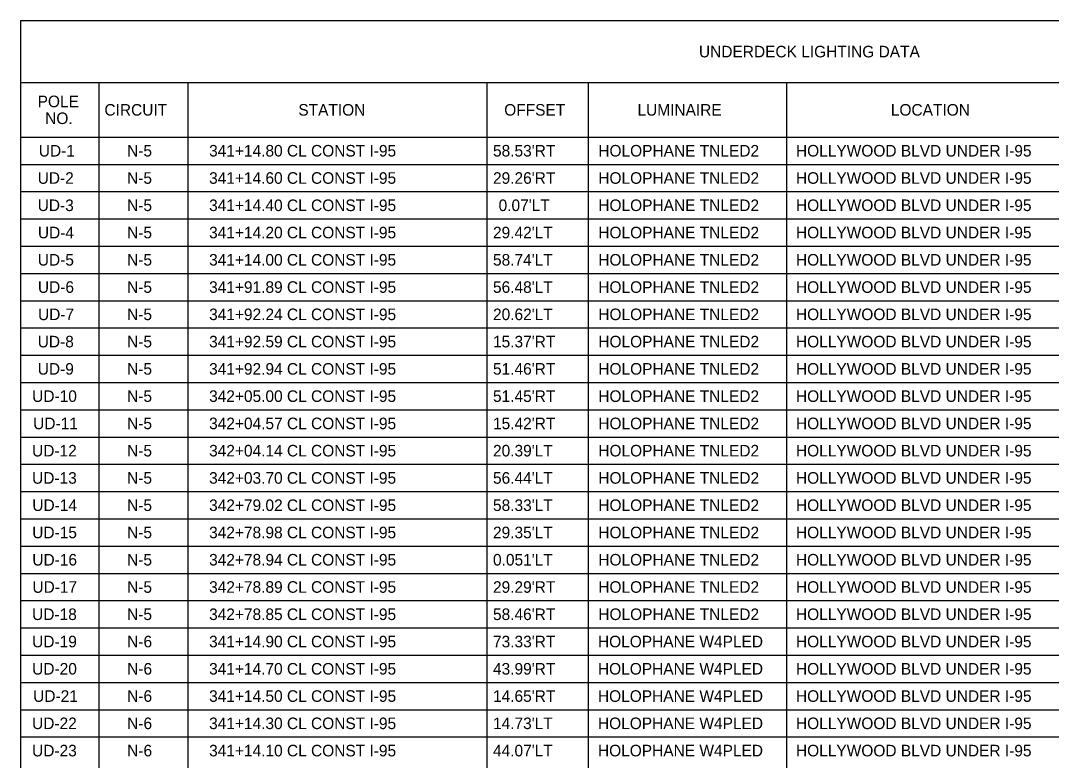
# Model space of a CAD drawing. Extents: x -816.7 to -727.6, y -2197.9 to -2187.8.
# Drawn here: x -777.1 to -770.86, y -2192.25 to -2187.77 of the extents above; entities that cross this region are included whole.
import ezdxf

# ---------------------------------------------------------------- set-up
doc = ezdxf.new("R2010")
doc.units = 0
for name, color, linetype in [('ClipBorder_dp', 7, 'Continuous'), ('MatchLines_dp', 7, 'Continuous'), ('NorthArw_dp', 7, 'Continuous'), ('Scale_dp', 7, 'Continuous')]:
    doc.layers.add(name, color=color, linetype=linetype)

msp = doc.modelspace()

# ---------------------------------------------------------------- linework, layer by layer
at = {"layer": 'MatchLines_dp'}
for p, q in [((-777.0968, -2188.4786), (-767.3318, -2188.4786)), ((-777.0968, -2188.6436), (-767.3318, -2188.6436)), ((-777.0968, -2188.6436), (-767.3318, -2188.6436)), ((-777.0968, -2188.8086), (-767.3318, -2188.8086)), ((-777.0968, -2188.8086), (-767.3318, -2188.8086)), ((-777.0968, -2188.9736), (-767.3318, -2188.9736)), ((-777.0968, -2188.9736), (-767.3318, -2188.9736)), ((-777.0968, -2189.1386), (-767.3318, -2189.1386)), ((-777.0968, -2189.1386), (-767.3318, -2189.1386)), ((-777.0968, -2189.3036), (-767.3318, -2189.3036)), ((-777.0968, -2189.3036), (-767.3318, -2189.3036)), ((-777.0968, -2189.4686), (-776.0843, -2189.4686)), ((-777.0968, -2189.4686), (-767.3318, -2189.4686)), ((-774.2768, -2189.4686), (-767.3318, -2189.4686)), ((-777.0968, -2189.6336), (-767.3318, -2189.6336)), ((-777.0968, -2189.6336), (-767.3318, -2189.6336)), ((-777.0968, -2189.7986), (-767.3318, -2189.7986)), ((-777.0968, -2189.7986), (-767.3318, -2189.7986)), ((-777.0968, -2189.9636), (-767.3318, -2189.9636)), ((-777.0968, -2189.9636), (-767.3318, -2189.9636)), ((-777.0968, -2190.1286), (-767.3318, -2190.1286)), ((-777.0968, -2190.1286), (-767.3318, -2190.1286)), ((-777.0968, -2190.2936), (-767.3318, -2190.2936)), ((-777.0968, -2190.2936), (-767.3318, -2190.2936)), ((-777.0968, -2190.4586), (-767.3318, -2190.4586)), ((-777.0968, -2190.4586), (-767.3318, -2190.4586)), ((-777.0968, -2190.6236), (-767.3318, -2190.6236)), ((-777.0968, -2190.6236), (-767.3318, -2190.6236)), ((-777.0968, -2190.7886), (-767.3318, -2190.7886)), ((-777.0968, -2190.7886), (-767.3318, -2190.7886)), ((-777.0968, -2190.9536), (-767.3318, -2190.9536)), ((-777.0968, -2190.9536), (-767.3318, -2190.9536)), ((-777.0968, -2191.1186), (-767.3318, -2191.1186)), ((-777.0968, -2191.1186), (-767.3318, -2191.1186)), ((-777.0968, -2191.2836), (-767.3318, -2191.2836)), ((-777.0968, -2191.2836), (-767.3318, -2191.2836)), ((-777.0968, -2191.4486), (-767.3318, -2191.4486)), ((-777.0968, -2191.4486), (-767.3318, -2191.4486)), ((-777.0968, -2191.6136), (-767.3318, -2191.6136)), ((-777.0968, -2191.6136), (-767.3318, -2191.6136)), ((-777.0968, -2191.7786), (-767.3318, -2191.7786)), ((-777.0968, -2191.7786), (-767.3318, -2191.7786)), ((-777.0968, -2191.9436), (-767.3318, -2191.9436)), ((-777.0968, -2191.9436), (-767.3318, -2191.9436)), ((-777.0968, -2192.1086), (-767.3318, -2192.1086)), ((-777.0968, -2192.1086), (-767.3318, -2192.1086))]:
    msp.add_line(p, q, dxfattribs=at)
at = {"layer": 'NorthArw_dp'}
for p, q in [((-777.0968, -2187.7736), (-767.3318, -2187.7736)), ((-777.0968, -2187.7736), (-777.0968, -2196.6761)), ((-777.0968, -2188.1486), (-767.3318, -2188.1486)), ((-777.0968, -2188.1486), (-767.3318, -2188.1486))]:
    msp.add_line(p, q, dxfattribs=at)
at = {"layer": 'Scale_dp'}
for p, q in [((-776.6243, -2188.1486), (-776.6243, -2196.6761)), ((-776.6243, -2188.1486), (-776.6243, -2196.6761)), ((-776.0843, -2188.1486), (-776.0843, -2196.6761)), ((-776.0843, -2188.1486), (-776.0843, -2196.6761)), ((-774.2768, -2188.1486), (-774.2768, -2189.3036)), ((-774.2768, -2188.1486), (-774.2768, -2196.6761)), ((-773.6618, -2188.1486), (-773.6618, -2196.6761)), ((-773.6618, -2188.1486), (-773.6618, -2196.6761)), ((-772.4618, -2188.1486), (-772.4618, -2196.6761)), ((-772.4618, -2188.1486), (-772.4618, -2196.6761)), ((-777.0968, -2188.4786), (-767.3318, -2188.4786)), ((-774.2768, -2189.4686), (-774.2768, -2196.6761))]:
    msp.add_line(p, q, dxfattribs=at)

# ---------------------------------------------------------------- texts
at = {"layer": 'ClipBorder_dp'}
for s, p in [('UNDERDECK LIGHTING DATA', (-772.9925, -2187.9961)), ('POLE', (-776.9939, -2188.2976)), ('CIRCUIT', (-776.5897, -2188.3486)), ('STATION', (-775.4164, -2188.3486)), ('OFFSET', (-774.1708, -2188.3486)), ('LUMINAIRE', (-773.3645, -2188.3486)), ('LOCATION', (-771.8315, -2188.3486)), ('NO.', (-776.9482, -2188.3996)), ('UD-1', (-776.9869, -2188.5961)), ('N-5', (-776.4526, -2188.5961)), ('341+14.80 CL CONST I-95', (-775.9564, -2188.5961)), ("58.53'RT", (-774.2386, -2188.5961)), ('HOLOPHANE TNLED2', (-773.6014, -2188.5961)), ('HOLLYWOOD BLVD UNDER I-95', (-772.4054, -2188.5961)), ('UD-2', (-776.9936, -2188.7611)), ('N-5', (-776.4526, -2188.7611)), ('341+14.60 CL CONST I-95', (-775.9564, -2188.7611)), ("29.26'RT", (-774.2386, -2188.7611)), ('HOLOPHANE TNLED2', (-773.6014, -2188.7611)), ('HOLLYWOOD BLVD UNDER I-95', (-772.4054, -2188.7611)), ('UD-3', (-776.9936, -2188.9261)), ('N-5', (-776.4526, -2188.9261)), ('341+14.40 CL CONST I-95', (-775.9564, -2188.9261)), ("0.07'LT", (-774.2047, -2188.9261)), ('HOLOPHANE TNLED2', (-773.6014, -2188.9261)), ('HOLLYWOOD BLVD UNDER I-95', (-772.4054, -2188.9261)), ('UD-4', (-776.9922, -2189.0911)), ('N-5', (-776.4526, -2189.0911)), ('341+14.20 CL CONST I-95', (-775.9564, -2189.0911)), ("29.42'LT", (-774.2386, -2189.0911)), ('HOLOPHANE TNLED2', (-773.6014, -2189.0911)), ('HOLLYWOOD BLVD UNDER I-95', (-772.4054, -2189.0911)), ('UD-5', (-776.9927, -2189.2561)), ('N-5', (-776.4526, -2189.2561)), ('341+14.00 CL CONST I-95', (-775.9564, -2189.2561)), ("58.74'LT", (-774.2386, -2189.2561)), ('HOLOPHANE TNLED2', (-773.6014, -2189.2561)), ('HOLLYWOOD BLVD UNDER I-95', (-772.4054, -2189.2561)), ('UD-6', (-776.9922, -2189.4211)), ('N-5', (-776.4526, -2189.4211)), ('341+91.89 CL CONST I-95', (-775.9564, -2189.4211)), ("56.48'LT", (-774.2386, -2189.4211)), ('HOLOPHANE TNLED2', (-773.6014, -2189.4211)), ('HOLLYWOOD BLVD UNDER I-95', (-772.4054, -2189.4211)), ('UD-7', (-776.9916, -2189.5861)), ('N-5', (-776.4526, -2189.5861)), ('341+92.24 CL CONST I-95', (-775.9564, -2189.5861)), ("20.62'LT", (-774.2386, -2189.5861)), ('HOLOPHANE TNLED2', (-773.6014, -2189.5861)), ('HOLLYWOOD BLVD UNDER I-95', (-772.4054, -2189.5861)), ('UD-8', (-776.9934, -2189.7511)), ('N-5', (-776.4526, -2189.7511)), ('341+92.59 CL CONST I-95', (-775.9564, -2189.7511)), ("15.37'RT", (-774.2386, -2189.7511)), ('HOLOPHANE TNLED2', (-773.6014, -2189.7511)), ('HOLLYWOOD BLVD UNDER I-95', (-772.4054, -2189.7511)), ('UD-9', (-776.9932, -2189.9161)), ('N-5', (-776.4526, -2189.9161)), ('341+92.94 CL CONST I-95', (-775.9564, -2189.9161)), ("51.46'RT", (-774.2386, -2189.9161)), ('HOLOPHANE TNLED2', (-773.6014, -2189.9161)), ('HOLLYWOOD BLVD UNDER I-95', (-772.4054, -2189.9161)), ('UD-10', (-777.0269, -2190.0811)), ('N-5', (-776.4526, -2190.0811)), ('342+05.00 CL CONST I-95', (-775.9564, -2190.0811)), ("51.45'RT", (-774.2386, -2190.0811)), ('HOLOPHANE TNLED2', (-773.6014, -2190.0811)), ('HOLLYWOOD BLVD UNDER I-95', (-772.4054, -2190.0811)), ('UD-11', (-777.0208, -2190.2461)), ('N-5', (-776.4526, -2190.2461)), ('342+04.57 CL CONST I-95', (-775.9564, -2190.2461)), ("15.42'RT", (-774.2386, -2190.2461)), ('HOLOPHANE TNLED2', (-773.6014, -2190.2461)), ('HOLLYWOOD BLVD UNDER I-95', (-772.4054, -2190.2461)), ('UD-12', (-777.0275, -2190.4111)), ('N-5', (-776.4526, -2190.4111)), ('342+04.14 CL CONST I-95', (-775.9564, -2190.4111)), ("20.39'LT", (-774.2386, -2190.4111)), ('HOLOPHANE TNLED2', (-773.6014, -2190.4111)), ('HOLLYWOOD BLVD UNDER I-95', (-772.4054, -2190.4111)), ('UD-13', (-777.0275, -2190.5761)), ('N-5', (-776.4526, -2190.5761)), ('342+03.70 CL CONST I-95', (-775.9564, -2190.5761)), ("56.44'LT", (-774.2386, -2190.5761)), ('HOLOPHANE TNLED2', (-773.6014, -2190.5761)), ('HOLLYWOOD BLVD UNDER I-95', (-772.4054, -2190.5761)), ('UD-14', (-777.0261, -2190.7411)), ('N-5', (-776.4526, -2190.7411)), ('342+79.02 CL CONST I-95', (-775.9564, -2190.7411)), ("58.33'LT", (-774.2386, -2190.7411)), ('HOLOPHANE TNLED2', (-773.6014, -2190.7411)), ('HOLLYWOOD BLVD UNDER I-95', (-772.4054, -2190.7411)), ('UD-15', (-777.0266, -2190.9061)), ('N-5', (-776.4526, -2190.9061)), ('342+78.98 CL CONST I-95', (-775.9564, -2190.9061)), ("29.35'LT", (-774.2386, -2190.9061)), ('HOLOPHANE TNLED2', (-773.6014, -2190.9061)), ('HOLLYWOOD BLVD UNDER I-95', (-772.4054, -2190.9061)), ('UD-16', (-777.0261, -2191.0711)), ('N-5', (-776.4526, -2191.0711)), ('342+78.94 CL CONST I-95', (-775.9564, -2191.0711)), ("0.051'LT", (-774.2386, -2191.0711)), ('HOLOPHANE TNLED2', (-773.6014, -2191.0711)), ('HOLLYWOOD BLVD UNDER I-95', (-772.4054, -2191.0711)), ('UD-17', (-777.0255, -2191.2361)), ('N-5', (-776.4526, -2191.2361)), ('342+78.89 CL CONST I-95', (-775.9564, -2191.2361)), ("29.29'RT", (-774.2386, -2191.2361)), ('HOLOPHANE TNLED2', (-773.6014, -2191.2361)), ('HOLLYWOOD BLVD UNDER I-95', (-772.4054, -2191.2361)), ('UD-18', (-777.0272, -2191.4011)), ('N-5', (-776.4526, -2191.4011)), ('342+78.85 CL CONST I-95', (-775.9564, -2191.4011)), ("58.46'RT", (-774.2386, -2191.4011)), ('HOLOPHANE TNLED2', (-773.6014, -2191.4011)), ('HOLLYWOOD BLVD UNDER I-95', (-772.4054, -2191.4011)), ('UD-19', (-777.0271, -2191.5661)), ('N-6', (-776.4521, -2191.5661)), ('341+14.90 CL CONST I-95', (-775.9564, -2191.5661)), ("73.33'RT", (-774.2386, -2191.5661)), ('HOLOPHANE W4PLED', (-773.6036, -2191.5661)), ('HOLLYWOOD BLVD UNDER I-95', (-772.4054, -2191.5661)), ('UD-20', (-777.0269, -2191.7311)), ('N-6', (-776.4521, -2191.7311)), ('341+14.70 CL CONST I-95', (-775.9564, -2191.7311)), ("43.99'RT", (-774.2386, -2191.7311)), ('HOLOPHANE W4PLED', (-773.6036, -2191.7311)), ('HOLLYWOOD BLVD UNDER I-95', (-772.4054, -2191.7311)), ('UD-21', (-777.0208, -2191.8961)), ('N-6', (-776.4521, -2191.8961)), ('341+14.50 CL CONST I-95', (-775.9564, -2191.8961)), ("14.65'RT", (-774.2386, -2191.8961)), ('HOLOPHANE W4PLED', (-773.6036, -2191.8961)), ('HOLLYWOOD BLVD UNDER I-95', (-772.4054, -2191.8961)), ('UD-22', (-777.0275, -2192.0611)), ('N-6', (-776.4521, -2192.0611)), ('341+14.30 CL CONST I-95', (-775.9564, -2192.0611)), ("14.73'LT", (-774.2386, -2192.0611)), ('HOLOPHANE W4PLED', (-773.6036, -2192.0611)), ('HOLLYWOOD BLVD UNDER I-95', (-772.4054, -2192.0611)), ('UD-23', (-777.0275, -2192.2261)), ('N-6', (-776.4521, -2192.2261)), ('341+14.10 CL CONST I-95', (-775.9564, -2192.2261)), ("44.07'LT", (-774.2386, -2192.2261)), ('HOLOPHANE W4PLED', (-773.6036, -2192.2261)), ('HOLLYWOOD BLVD UNDER I-95', (-772.4054, -2192.2261))]:
    msp.add_text(s, height=0.07, dxfattribs=at).set_placement(p)

doc.saveas('drawing.dxf')
